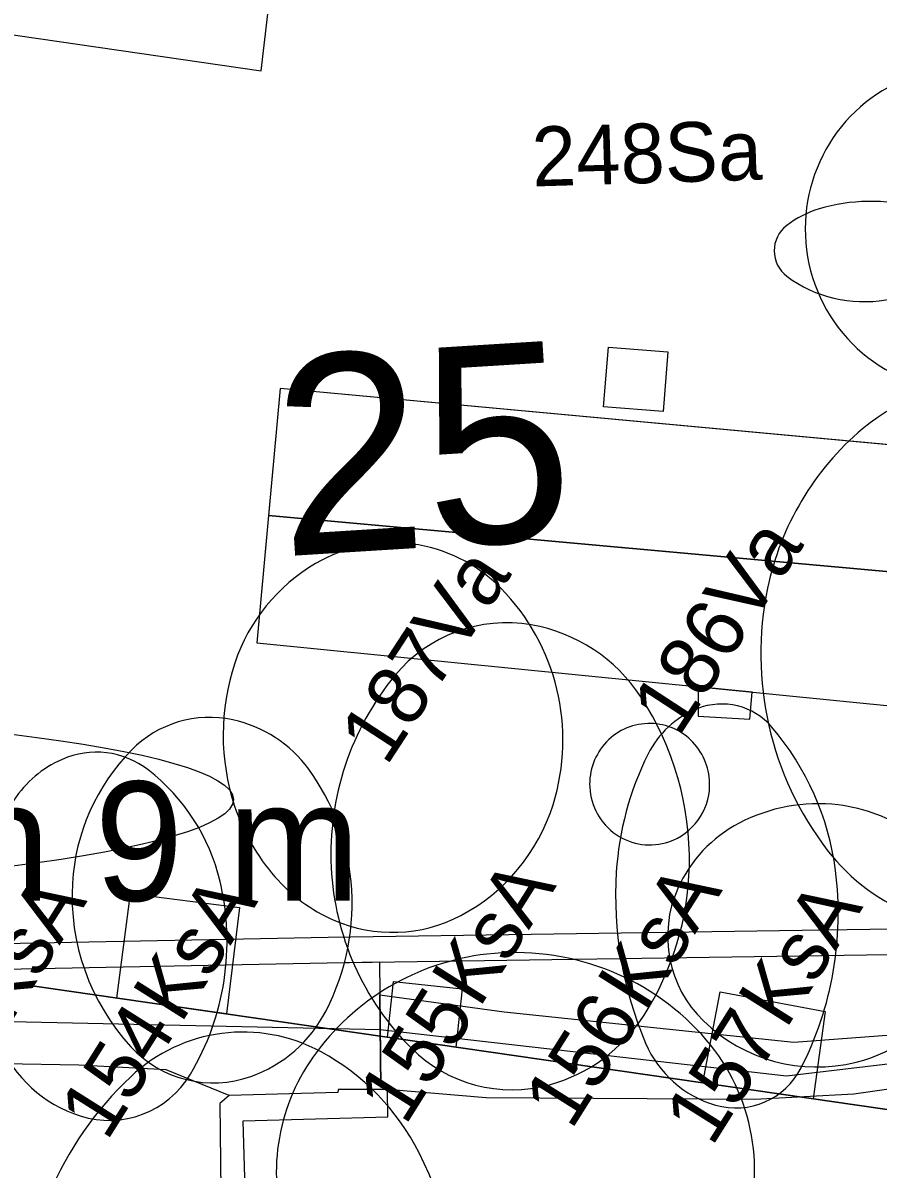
# Model space of a CAD drawing. Extents: x 738423 to 738903, y 6589762 to 6590172.
# Drawn here: x 738661.32 to 738682.86, y 6589875.99 to 6589904.84 of the extents above; entities that cross this region are included whole.
import ezdxf

# ---------------------------------------------------------------- set-up
doc = ezdxf.new("R2010")
doc.units = 0
for name, color, linetype in [('_1927_hoonestus', 7, 'Continuous'), ('_1927_katuse_kalded', 7, 'Continuous'), ('_1927_kvartali_nr_planžetil', 7, 'Continuous'), ('_a_olol_maapind', 7, 'Continuous'), ('a_dendro_II_Vkl_puu', 7, 'Continuous'), ('a_dendro_III_vk_puu', 7, 'Continuous'), ('a_dendro_puu_nr', 7, 'Continuous'), ('a_dendro_V_vk_puu', 7, 'Continuous'), ('Default', 7, 'Continuous'), ('v_dp_jalak_liikumine', 7, 'Continuous'), ('v_olol_kivimuur', 7, 'Continuous'), ('v_olol_transp_jjt_jalg', 7, 'Continuous')]:
    doc.layers.add(name, color=color, linetype=linetype)

# ---------------------------------------------------------------- blocks, each defined once
blk = doc.blocks.new('_U578')
at = {"layer": 'Default'}
for centre, radius, start, end in [((0.0031046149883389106, 0.0007126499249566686), 0.010083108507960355, 58.964104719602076, 112.89361314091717), ((0.003381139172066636, 5.782187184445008e-05), 0.010793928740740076, 112.89361314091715, 149.17299112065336), ((0.0018851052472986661, -0.001314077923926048), 0.01244844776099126, 10.793615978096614, 58.964104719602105), ((0.005224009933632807, -0.001041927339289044), 0.012939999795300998, 149.1729911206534, 182.21275775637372), ((0.0016087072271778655, -0.0013667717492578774), 0.012729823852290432, 316.8121326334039, 10.793615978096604), ((0.005405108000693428, -0.0010349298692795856), 0.013121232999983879, 182.2127577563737, 217.26007191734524), ((0.0036931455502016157, -0.0023372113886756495), 0.010970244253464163, 217.26007191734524, 255.71243530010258), ((0.0034904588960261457, -0.0031331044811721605), 0.010148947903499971, 255.71243530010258, 316.8121326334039)]:
    blk.add_arc(centre, radius, start, end, dxfattribs=at)
blk = doc.blocks.new('_U577')
at = {"layer": 'Default'}
for centre, radius, start, end in [((0.0003509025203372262, -0.0024429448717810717), 0.017498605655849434, 47.6139328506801, 95.06339460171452), ((0.0003539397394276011, -0.0024772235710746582), 0.01753301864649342, 95.06339460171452, 143.64928581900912), ((0.006587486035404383, 0.004390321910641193), 0.008247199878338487, 335.85757945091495, 47.613932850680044), ((-0.007106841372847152, 0.0030134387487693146), 0.008269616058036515, 143.6492858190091, 217.25092224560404), ((0.00326511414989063, 0.0058794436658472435), 0.011888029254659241, 301.16151048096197, 335.85757945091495), ((-0.004085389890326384, 0.00531108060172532), 0.012065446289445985, 217.2509222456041, 249.96613917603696), ((-0.0012283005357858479, 0.013310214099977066), 0.02057175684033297, 274.9595126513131, 301.16151048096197), ((-0.0012168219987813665, 0.01317793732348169), 0.020438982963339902, 249.96613917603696, 274.9595126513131)]:
    blk.add_arc(centre, radius, start, end, dxfattribs=at)
blk = doc.blocks.new('_U603')
at = {"layer": 'Default'}
for centre, radius, start, end in [((-0.0017965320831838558, -0.010040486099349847), 0.014131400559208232, 84.19507760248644, 117.35483362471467), ((-0.0014956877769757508, -0.007081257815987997), 0.01115691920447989, 61.01745587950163, 84.19507760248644), ((-0.005240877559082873, -0.003382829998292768), 0.0066355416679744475, 117.35483362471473, 166.57279405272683), ((0.0012008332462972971, -0.0022131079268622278), 0.005591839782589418, 28.048391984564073, 61.017455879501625), ((0.0023609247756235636, -0.0015950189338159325), 0.0042773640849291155, 326.65781354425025, 28.048391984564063), ((-0.007049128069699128, -0.002951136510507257), 0.004776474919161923, 166.57279405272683, 243.48107124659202), ((-0.002429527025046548, 0.001556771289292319), 0.010011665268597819, 287.6753935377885, 326.6578135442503), ((-0.0033532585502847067, 0.004455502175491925), 0.0130540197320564, 243.48107124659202, 287.6753935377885)]:
    blk.add_arc(centre, radius, start, end, dxfattribs=at)
blk = doc.blocks.new('_U604')
at = {"layer": 'Default'}
for centre, radius, start, end in [((-0.0004852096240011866, -0.0031711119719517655), 0.011179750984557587, 90.93532213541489, 137.03604495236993), ((-0.0004976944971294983, -0.002406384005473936), 0.010414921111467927, 49.7779983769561, 90.93532213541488), ((0.0026628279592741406, 0.0013306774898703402), 0.00552058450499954, 352.04332547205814, 49.77799837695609), ((-0.0045278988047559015, 0.0005940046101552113), 0.005655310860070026, 137.03604495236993, 203.83985805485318), ((0.001762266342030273, 0.0014565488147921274), 0.006429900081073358, 310.51471278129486, 352.04332547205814), ((-0.00346779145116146, 0.0010624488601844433), 0.0068143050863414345, 203.83985805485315, 247.08044384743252), ((-0.0014073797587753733, 0.005165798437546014), 0.011308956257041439, 279.50459050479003, 310.5147127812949), ((-0.001499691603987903, 0.005717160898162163), 0.011867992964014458, 247.0804438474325, 279.50459050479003)]:
    blk.add_arc(centre, radius, start, end, dxfattribs=at)
blk = doc.blocks.new('_U605')
at = {"layer": 'Default'}
for centre, radius, start, end in [((0.0008773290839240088, -0.0036700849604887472), 0.013776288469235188, 97.06851750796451, 139.45674043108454), ((0.0009208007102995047, -0.004020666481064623), 0.014129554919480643, 54.774629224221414, 97.06851750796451), ((0.004869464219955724, 0.0015716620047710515), 0.007283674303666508, 354.44775722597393, 54.77462922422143), ((-0.004142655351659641, 0.0006239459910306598), 0.007170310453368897, 139.45674043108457, 199.6047236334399), ((0.0038669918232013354, 0.0016691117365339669), 0.008290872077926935, 307.557172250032, 354.44775722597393), ((-0.0031368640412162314, 0.0009821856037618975), 0.008237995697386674, 199.60472363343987, 241.6838679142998), ((-0.00019873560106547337, 0.006956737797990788), 0.01496088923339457, 273.09970195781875, 307.557172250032), ((-0.00017307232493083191, 0.006482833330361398), 0.014486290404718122, 241.68386791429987, 273.09970195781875)]:
    blk.add_arc(centre, radius, start, end, dxfattribs=at)
blk = doc.blocks.new('_U606')
at = {"layer": 'Default'}
for centre, radius, start, end in [((-0.00014779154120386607, -0.014920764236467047), 0.01894048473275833, 90.66390799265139, 117.35483362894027), ((-0.000187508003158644, -0.011493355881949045), 0.015512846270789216, 67.89150399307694, 90.66390799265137), ((0.0038622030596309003, -0.0015243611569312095), 0.004752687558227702, 26.099496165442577, 67.89150399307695), ((-0.006334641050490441, -0.002962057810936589), 0.005476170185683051, 117.35483362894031, 168.19775188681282), ((0.005147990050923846, -0.000894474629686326), 0.0033209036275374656, 314.8352952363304, 26.09949616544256), ((-0.00807806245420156, -0.0025977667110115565), 0.003695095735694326, 168.19775188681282, 247.1920387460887), ((-0.0022563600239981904, 0.006552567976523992), 0.013822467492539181, 281.65124419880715, 314.8352952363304), ((-0.002905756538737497, 0.009701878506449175), 0.017038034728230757, 247.19203874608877, 281.65124419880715)]:
    blk.add_arc(centre, radius, start, end, dxfattribs=at)
blk = doc.blocks.new('_U607')
at = {"layer": 'Default'}
for centre, radius, start, end in [((-0.0026566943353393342, 0.002417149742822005), 0.005933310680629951, 70.41382597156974, 140.13835243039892), ((-0.0029635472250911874, 0.0015547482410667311), 0.006848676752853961, 31.851207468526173, 70.41382597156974), ((-0.0009113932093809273, 0.0009598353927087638), 0.008207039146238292, 140.13835243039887, 198.29664430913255), ((-0.004453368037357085, 0.0006291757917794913), 0.008602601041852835, 357.58074074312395, 31.8512074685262), ((-0.004046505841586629, 0.0006119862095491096), 0.008195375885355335, 329.5158395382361, 357.58074074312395), ((-0.0014782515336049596, 0.0007724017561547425), 0.007609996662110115, 198.29664430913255, 244.4976123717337), ((-0.0025724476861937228, -0.00025575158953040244), 0.006484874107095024, 297.8801249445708, 329.51583953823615), ((-0.0022549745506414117, -0.0008558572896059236), 0.005805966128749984, 244.49761237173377, 297.8801249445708)]:
    blk.add_arc(centre, radius, start, end, dxfattribs=at)
blk = doc.blocks.new('_U635')
at = {"layer": 'Default'}
for centre, radius, start, end in [((-0.0030800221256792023, -0.004084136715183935), 0.01621807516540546, 82.51786558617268, 131.80255217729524), ((-0.002834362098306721, -0.0022136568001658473), 0.014331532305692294, 44.52272470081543, 82.51786558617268), ((-0.007166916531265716, 0.0004863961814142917), 0.010086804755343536, 131.80255217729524, 195.63791634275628), ((0.0005540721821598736, 0.0011187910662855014), 0.009578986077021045, 357.5943351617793, 44.52272470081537), ((-1.0473925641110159e-05, 0.0011425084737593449), 0.010144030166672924, 318.7914036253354, 357.5943351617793), ((-0.006344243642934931, 0.000716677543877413), 0.010941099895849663, 195.63791634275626, 246.29930243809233), ((-0.0035940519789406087, 0.0042806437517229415), 0.014907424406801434, 286.9840068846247, 318.7914036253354), ((-0.004080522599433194, 0.005873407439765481), 0.016572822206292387, 246.2993024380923, 286.9840068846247)]:
    blk.add_arc(centre, radius, start, end, dxfattribs=at)
blk = doc.blocks.new('_U636')
at = {"layer": 'Default'}
for centre, radius, start, end in [((0.00010175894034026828, -2.919572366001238e-05), 0.003075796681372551, 97.35783492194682, 149.88923736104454), ((0.00010187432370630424, -3.0089274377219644e-05), 0.0030766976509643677, 50.52505287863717, 97.35783492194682), ((0.00015430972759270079, 3.3576655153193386e-05), 0.0029942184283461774, 3.012518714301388, 50.525052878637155), ((2.8773530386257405e-05, 1.3130757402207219e-05), 0.0029914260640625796, 149.8892373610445, 203.21391915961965), ((0.00014157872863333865, 3.2906662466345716e-05), 0.0030069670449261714, 317.6071516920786, 3.012518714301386), ((4.6031900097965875e-05, 2.0532667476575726e-05), 0.0030102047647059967, 203.21391915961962, 238.22626088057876), ((8.244964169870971e-05, 8.68854055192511e-05), 0.0030870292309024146, 272.8268339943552, 317.60715169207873), ((8.279522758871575e-05, 7.98865707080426e-05), 0.0030800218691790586, 238.2262608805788, 272.8268339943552)]:
    blk.add_arc(centre, radius, start, end, dxfattribs=at)
blk = doc.blocks.new('_U637')
at = {"layer": 'Default'}
for centre, radius, start, end in [((0.004024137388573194, -0.006515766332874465), 0.011412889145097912, 75.83447854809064, 112.62977376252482), ((0.004574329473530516, -0.004335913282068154), 0.009164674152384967, 34.59052716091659, 75.83447854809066), ((0.0036359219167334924, -0.005584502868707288), 0.010403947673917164, 112.62977376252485, 135.346483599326), ((0.002192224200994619, -0.004158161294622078), 0.008374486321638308, 135.34648359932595, 160.70759621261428), ((0.005810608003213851, -0.003483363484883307), 0.0076629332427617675, 318.87708210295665, 34.59052716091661), ((0.0012611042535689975, -0.0038322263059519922), 0.007387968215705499, 160.70759621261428, 212.04592843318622), ((0.00306175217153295, -0.0027050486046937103), 0.009512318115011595, 212.0459284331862, 256.9304777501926), ((0.003374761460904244, -0.001356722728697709), 0.010896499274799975, 256.9304777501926, 318.87708210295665)]:
    blk.add_arc(centre, radius, start, end, dxfattribs=at)
blk = doc.blocks.new('_U694')
at = {"layer": 'Default'}
for centre, radius, start, end in [((0.0004283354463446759, -0.0021435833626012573), 0.008211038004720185, 96.61449276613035, 136.42007091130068), ((0.00042891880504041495, -0.0021486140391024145), 0.008216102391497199, 57.797497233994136, 96.61449276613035), ((0.0005495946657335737, -0.0019570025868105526), 0.007989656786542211, 18.41186471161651, 57.79749723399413), ((0.0002597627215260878, -0.001983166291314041), 0.007978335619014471, 136.4200709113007, 176.82690829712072), ((0.0006022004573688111, -0.0019394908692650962), 0.007934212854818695, 325.04588222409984, 18.411864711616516), ((0.00021332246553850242, -0.0019805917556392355), 0.007931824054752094, 176.8269082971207, 225.1076301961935), ((0.000388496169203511, -0.001790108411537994), 0.008194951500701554, 272.6016373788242, 325.04588222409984), ((0.00038913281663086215, -0.0018041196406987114), 0.008180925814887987, 225.10763019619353, 272.6016373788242)]:
    blk.add_arc(centre, radius, start, end, dxfattribs=at)
blk = doc.blocks.new('_U695')
at = {"layer": 'Default'}
for centre, radius, start, end in [((-0.0015650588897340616, 0.0029536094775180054), 0.001602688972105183, 41.6369302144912, 147.50245663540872), ((0.0024974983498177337, 0.0003657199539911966), 0.006419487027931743, 147.50245663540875, 194.49544515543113), ((-0.004182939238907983, 0.000626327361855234), 0.0051054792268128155, 20.879218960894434, 41.63693021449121), ((-0.008013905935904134, -0.0008349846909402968), 0.00920569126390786, 5.45854421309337, 20.87921896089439), ((-0.007349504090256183, -0.0007714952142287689), 0.008538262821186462, 348.2349755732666, 5.458544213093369), ((0.0013873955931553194, 7.872201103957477e-05), 0.005272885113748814, 194.4954451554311, 235.65025016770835), ((-0.002420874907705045, -0.0017979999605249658), 0.003503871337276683, 321.1995092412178, 348.2349755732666), ((-0.0007908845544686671, -0.003108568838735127), 0.0014123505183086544, 235.65025016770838, 321.1995092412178)]:
    blk.add_arc(centre, radius, start, end, dxfattribs=at)

msp = doc.modelspace()

# ---------------------------------------------------------------- linework, layer by layer
at = {"layer": '_1927_hoonestus'}
for points in [[(738655.3410315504, 6589908.260938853), (738655.0571223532, 6589905.406639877), (738667.3213049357, 6589903.626637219), (738667.6613666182, 6589906.503844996)], [(738676.0694962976, 6589896.673562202), (738677.5697628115, 6589896.553270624), (738677.4494712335, 6589895.05300411), (738675.9492047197, 6589895.173295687)], [(738694.0108549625, 6589893.210446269), (738667.804973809, 6589895.634829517), (738667.2127800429, 6589889.233630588), (738685.1046234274, 6589887.453898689), (738685.1578836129, 6589887.989329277), (738692.7143690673, 6589887.27516718)], [(738678.3332683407, 6589888.127456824), (738678.3332683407, 6589887.384994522), (738679.6298013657, 6589887.311684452), (738679.6877577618, 6589887.9927234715)], [(738663.6901618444, 6589880.291598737), (738664.0324354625, 6589882.926377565), (738666.7757054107, 6589882.570010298), (738666.4500033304, 6589879.892616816)], [(738686.9079452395, 6589860.693508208), (738690.3471033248, 6589876.437885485), (738655.8073303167, 6589881.431195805), (738653.971798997, 6589865.440014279)], [(738670.5022608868, 6589879.3067942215), (738670.6527014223, 6589880.710547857), (738672.3870423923, 6589880.524678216), (738672.2264895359, 6589879.057527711)], [(738678.4496088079, 6589878.157870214), (738678.8809208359, 6589880.448536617), (738681.5320348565, 6589879.949355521), (738681.2281067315, 6589877.756191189)]]:
    msp.add_lwpolyline(points, close=True, dxfattribs=at)
at = {"layer": '_1927_katuse_kalded'}
for points in [[(738685.7580226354, 6589890.785679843), (738686.4289503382, 6589893.911870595), (738667.804973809, 6589895.634829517), (738667.5088769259, 6589892.434230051)], [(738685.1046234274, 6589887.453898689), (738685.1578836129, 6589887.989329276), (738685.7580226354, 6589890.785679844), (738667.508876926, 6589892.434230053), (738667.2127800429, 6589889.233630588)], [(738654.1081769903, 6589873.783129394), (738655.0056644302, 6589881.575610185), (738655.8073303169, 6589881.431195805), (738690.3471033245, 6589876.437885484), (738688.7887442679, 6589869.303757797)]]:
    msp.add_lwpolyline(points, close=True, dxfattribs=at)
at = {"layer": 'a_dendro_V_vk_puu'}
msp.add_ellipse((738647.6051953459, 6589885.222999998), major_axis=(19.017612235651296, 0.06685041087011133), ratio=0.12347597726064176, dxfattribs=at)
at = {"layer": 'v_dp_jalak_liikumine'}
msp.add_lwpolyline([(738581.4723412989, 6589878.120522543), (738587.4015406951, 6589878.120522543), (738606.5184403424, 6589878.608756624), (738618.5434188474, 6589878.425595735), (738641.8496480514, 6589878.136204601), (738655.9728153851, 6589879.813491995), (738670.3230528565, 6589879.497843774), (738680.5529887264, 6589878.338003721), (738697.9581193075, 6589880.397873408), (738705.6932562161, 6589881.082962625), (738725.5888177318, 6589880.833839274), (738742.0007790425, 6589880.833839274), (738745.4047050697, 6589880.7783847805), (738754.5304628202, 6589882.343075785), (738758.8441211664, 6589885.746853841)], dxfattribs=at)
at = {"layer": 'v_olol_kivimuur'}
msp.add_lwpolyline([(738659.9889999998, 6589880.999), (738668.9849999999, 6589881.181999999), (738685.9700000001, 6589881.434000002), (738699.3649999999, 6589881.647999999), (738707.9990000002, 6589881.8900000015), (738716.541, 6589882.000000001), (738723.847358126, 6589882.143855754), (738735.8410000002, 6589882.379999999), (738754.0880000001, 6589882.902), (738754.024, 6589883.413000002), (738735.8970000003, 6589882.9909999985), (738716.5100000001, 6589882.6219999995), (738707.99, 6589882.534999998), (738699.5579999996, 6589882.3539999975), (738686.0599999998, 6589882.071000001), (738669.01, 6589881.818000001), (738666.875, 6589881.770000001), (738659.944, 6589881.638000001)], dxfattribs=at)
msp.add_lwpolyline([(738670.507, 6589877.989), (738669.2659999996, 6589877.994000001), (738669.256, 6589877.913000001), (738666.5159999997, 6589877.836), (738666.2819999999, 6589877.638000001), (738666.319, 6589874.704), (738666.3879999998, 6589865.342000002), (738666.6002612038, 6589839.331603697), (738667.2190409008, 6589839.230293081), (738667.0289999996, 6589865.218000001), (738666.944, 6589874.627999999), (738666.871, 6589877.199999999), (738670.5099999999, 6589877.303999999)], close=True, dxfattribs=at)
at = {"layer": 'v_olol_transp_jjt_jalg'}
for points in [[(738659.9889999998, 6589880.999), (738668.9849999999, 6589881.181999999), (738670.3032881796, 6589881.201558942), (738670.34, 6589878.036999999), (738670.34, 6589878.036999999), (738670.3128629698, 6589880.376211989), (738673.4449999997, 6589879.948), (738680.7409005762, 6589879.183086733), (738687.2215764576, 6589879.67051432), (738697.799, 6589881.108999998), (738699.3649999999, 6589881.647999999)], [(738699.0990000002, 6589879.646000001), (738693.2890000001, 6589879.360999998), (738686.0879999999, 6589878.418), (738682.2479999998, 6589877.876000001), (738679.7519999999, 6589877.738000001), (738672.9870000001, 6589877.782), (738670.507, 6589877.988999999), (738669.2659999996, 6589877.994000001), (738669.256, 6589877.913000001), (738666.5159999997, 6589877.835999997), (738664.931, 6589878.489), (738662.7329999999, 6589878.602000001), (738660.8409999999, 6589878.633999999)]]:
    msp.add_lwpolyline(points, dxfattribs=at)

# ---------------------------------------------------------------- block references
at = {"layer": 'a_dendro_II_Vkl_puu', "xscale": 500.0000000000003, "yscale": 500.0000000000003, "rotation": 85.69234851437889}
for name, p in [('_U604', (738666.587, 6589883.218000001)), ('_U607', (738681.8327824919, 6589883.078)), ('_U578', (738672.9843105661, 6589874.321442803)), ('_U577', (738668.8083105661, 6589871.8624428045))]:
    msp.add_blockref(name, p, dxfattribs=at)
at = {"layer": 'a_dendro_III_vk_puu', "xscale": 500.0000000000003, "yscale": 500.0000000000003, "rotation": 85.69234851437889}
for name, p in [('_U694', (738684.0480000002, 6589899.514000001)), ('_U635', (738686.0960000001, 6589890.641000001)), ('_U605', (738674.105, 6589883.609999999)), ('_U606', (738678.286, 6589883.499)), ('_U603', (738662.2849999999, 6589883.225000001))]:
    msp.add_blockref(name, p, dxfattribs=at)
at = {"layer": 'a_dendro_V_vk_puu', "xscale": 500.0000000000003, "yscale": 500.0000000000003, "rotation": 85.69234851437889}
for name, p in [('_U695', (738682.577, 6589899.7700000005)), ('_U637', (738668.6726217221, 6589885.154360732)), ('_U636', (738677.1159999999, 6589885.6272789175))]:
    msp.add_blockref(name, p, dxfattribs=at)

# ---------------------------------------------------------------- texts
at = {"layer": '_1927_kvartali_nr_planžetil'}
msp.add_text('25', height=4.999999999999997, rotation=3.560863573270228, dxfattribs=at).set_placement((738667.8429261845, 6589891.40771169))
at = {"layer": '_a_olol_maapind'}
msp.add_text('räästajoon 9 m', height=3, dxfattribs=at).set_placement((738643.2807664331, 6589882.74118056))
at = {"layer": 'a_dendro_puu_nr'}
for s, height, rotation, p in [('248Sa', 1.5, 1.7381147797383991, (738674.1615719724, 6589900.7175935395)), ('186Va', 1.5000000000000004, 56.88665020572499, (738677.8383151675, 6589886.840101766)), ('187Va', 1.5000000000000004, 56.88665020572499, (738670.4769749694, 6589886.1009146)), ('KsA', 1.5000000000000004, 57.784522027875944, (738672.8150811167, 6589880.011746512)), ('KsA', 1.5000000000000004, 57.784522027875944, (738676.9960811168, 6589879.90074651)), ('KsA', 1.5000000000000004, 57.784522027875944, (738660.9950811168, 6589879.626746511)), ('KsA', 1.5000000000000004, 57.784522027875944, (738665.2970811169, 6589879.619746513)), ('KsA', 1.5000000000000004, 57.784522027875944, (738680.5370811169, 6589879.47974651)), ('155', 1.5000000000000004, 57.784522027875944, (738670.9512141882, 6589877.053748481)), ('156', 1.5000000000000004, 57.784522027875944, (738675.1322141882, 6589876.9427484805)), ('154', 1.5000000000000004, 57.784522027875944, (738663.4332141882, 6589876.661748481)), ('157', 1.5000000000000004, 57.784522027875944, (738678.6732141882, 6589876.52174848))]:
    msp.add_text(s, height=height, rotation=rotation, dxfattribs=at).set_placement(p)

doc.saveas('drawing.dxf')
